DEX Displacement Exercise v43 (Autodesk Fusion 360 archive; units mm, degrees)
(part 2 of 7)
sketch "Sketch3" plane through (0, 0, 0) normal (1, 0, 0) x axis (0, 1, 0)
  line L1 (0, -98.35) -> (0, 35.65)
  line L2 (600, -98.35) -> (0, -98.35)
  line L3 (600, 35.65) -> (600, -98.35)
  line L4 (600, 35.65) -> (0, 35.65)
  line L5 (580, 20.65) -> (600, 20.65)
  line L6 (580, 35.65) -> (580, 20.65)
  line L7 (20, 20.65) -> (0, 20.65)
  line L8 (20, 35.65) -> (20, 20.65)
  line L9 (580, -83.35) -> (580, -98.35)
  line L10 (600, -83.35) -> (580, -83.35)
  line L11 (10, -83.35) -> (0, -83.35)
  line L12 (10, -48.35) -> (10, -83.35)
  line L13 (45, -48.35) -> (10, -48.35)
  line L14 (45, -83.35) -> (45, -48.35)
  line L15 (65, -83.35) -> (45, -83.35)
  line L16 (65, -98.35) -> (65, -83.35)
  line L17 (27.5, -48.35) -> (27.5, -68.65)
  line L18 (27.5, -68.65) -> (4.7, -98.65)
  line L19 (50.3, -98.65) -> (27.5, -68.65)
  line L20 (114.9, -83.45) -> (54.9, -83.45)
  line L21 (114.9, -23.45) -> (114.9, -83.45)
  line L22 (54.9, -23.45) -> (114.9, -23.45)
  line L23 (54.9, -83.45) -> (54.9, -23.45)
  line L24 (430, -48.35) -> (520, -48.35)
  line L25 (430, -78.35) -> (430, -48.35)
  line L26 (520, -78.35) -> (430, -78.35)
  line L27 (520, -48.35) -> (520, -78.35)
  line L28 (140, -48.35) -> (230, -48.35)
  line L29 (140, -78.35) -> (140, -48.35)
  line L30 (230, -78.35) -> (140, -78.35)
  line L31 (230, -48.35) -> (230, -78.35)
  line L32 (285, -78.35) -> (375, -78.35)
  line L33 (285, -48.35) -> (285, -78.35)
  line L34 (375, -48.35) -> (285, -48.35)
  line L35 (375, -78.35) -> (375, -48.35)
  circle C1 centre (4.7, -98.65) radius 9.7
  circle C2 centre (27.5, -68.65) radius 11.4592
  circle C3 centre (50.3, -98.65) radius 9.7
  circle C4 centre (27.5, -68.65) radius 40
  circle C5 centre (4.7, 35.95) radius 9.7
  circle C6 centre (595.3, 35.95) radius 9.7
  circle C7 centre (595.3, -98.65) radius 9.7
  circle C8 centre (595, 15.65) radius 1.575
  circle C9 centre (575, 15.65) radius 1.575
  circle C10 centre (575, 30.65) radius 1.575
  circle C11 centre (25, 30.65) radius 1.575
  circle C12 centre (25, 15.65) radius 1.575
  circle C13 centre (5, 15.65) radius 1.575
  circle C14 centre (595, -78.35) radius 1.575
  circle C15 centre (575, -78.35) radius 1.575
  circle C16 centre (575, -93.35) radius 1.575
  circle C17 centre (5, -78.35) radius 1.575
  circle C18 centre (70, -93.35) radius 1.575
  circle C19 centre (50, -43.35) radius 1.575
  circle C20 centre (5, -43.35) radius 1.575
  circle C21 centre (50, 25) radius 1.575
  circle C22 centre (65, 25) radius 1.575
  circle C23 centre (75, 25) radius 1.575
  circle C24 centre (90, 25) radius 1.575
  circle C25 centre (90, 17) radius 1.575
  circle C26 centre (75, 17) radius 1.575
  circle C27 centre (65, 17) radius 1.575
  circle C28 centre (50, 17) radius 1.575
  circle C29 centre (120, -93.35) radius 1.575
  circle C30 centre (120, -28.35) radius 1.575
  circle C31 centre (5, -28.35) radius 1.575
  circle C32 centre (50, -28.35) radius 1.575
  circle C33 centre (50, -78.35) radius 1.575
  circle C34 centre (5, -7.5) radius 1.575
  circle C35 centre (25, -7.5) radius 1.575
  circle C36 centre (510, 17) radius 1.575
  circle C37 centre (535, 17) radius 1.575
  circle C38 centre (510, 25) radius 1.575
  circle C39 centre (535, 25) radius 1.575
  circle C40 centre (525, 17) radius 1.575
  circle C41 centre (550, 25) radius 1.575
  circle C42 centre (550, 17) radius 1.575
  circle C43 centre (525, 25) radius 1.575
  point P2 (4.7, -98.65)
  point P4 (50.3, -98.65)
  point P9 (4.7, 35.95)
  point P10 (595.3, 35.95)
  point P11 (595.3, -98.65)
  point P13 (600, 20.65)
  point P15 (580, 35.65)
  point P16 (595, 15.65)
  point P17 (575, 15.65)
  point P18 (575, 30.65)
  point P20 (0, 20.65)
  point P22 (20, 35.65)
  point P24 (25, 15.65)
  point P25 (5, 15.65)
  point P23 (25, 30.65)
  point P26 (580, -98.35)
  point P28 (600, -83.35)
  point P29 (595, -78.35)
  point P30 (575, -78.35)
  point P31 (575, -93.35)
  point P32 (605, 35.95)
  point P33 (-5, -98.65)
  point P34 (0, -83.35)
  point P40 (65, -98.35)
  point P5 (27.5, -68.65)
  point P41 (27.5, -68.65)
  point P42 (27.5, -48.35)
  point P43 (4.7, -98.65)
  point P3 (27.5, -68.65)
  point P44 (27.5, -68.65)
  point P45 (27.5, -68.65)
  point P46 (50.3, -98.65)
  point P35 (10, -83.35)
  point P56 (75, 17)
  point P57 (65, 17)
  point P58 (50, 17)
  point P55 (90, 17)
  point P51 (50, 25)
  point P53 (75, 25)
  point P54 (90, 25)
  point P52 (65, 25)
  point P49 (50, -43.35)
  point P63 (50, -78.35)
  point P50 (5, -43.35)
  point P62 (50, -28.35)
  point P61 (5, -28.35)
  point P60 (120, -28.35)
  point P48 (70, -93.35)
  point P59 (120, -93.35)
  point P68 (5, -7.5)
  point P69 (25, -7.5)
  point P75 (525, 17)
  point P77 (535, 17)
  point P72 (510, 17)
  point P73 (550, 17)
  point P71 (510, 25)
  point P74 (535, 25)
  point P76 (550, 25)
  point P70 (525, 25)
  point P80 (430, -78.35)
  point P79 (430, -48.35)
  point P85 (230, -78.35)
  point P6 (0, 35.65)
  point P1 (0, 0)
  point P7 (0, -98.35)
  point P36 (10, -48.35)
  point P37 (45, -48.35)
  point P38 (45, -83.35)
  point P39 (65, -83.35)
  point P47 (5, -78.35)
  point P64 (54.9, -83.45)
  point P65 (114.9, -83.45)
  point P81 (520, -78.35)
  point P78 (520, -48.35)
  point P86 (375, -78.35)
  equal C1 C3
  horizontal P2 P4
  concentric C2 C4
  equal C1 C7
  equal C1 C6
  equal C1 C5
  horizontal P9 P10
  vertical P2 P9
  vertical P10 P11
  coincident L3 P13
  perpendicular L3 L5
  coincident L4 P15
  perpendicular L4 L6
  horizontal P16 P17
  vertical P17 P18
  equal C9 C10
  equal C8 C10
  coincident L1 P20
  perpendicular L1 L7
  coincident L4 P22
  perpendicular L4 L8
  horizontal P24 P25
  vertical P23 P24
  equal C12 C13
  equal C11 C12
  equal C9 C12
  coincident L2 P26
  perpendicular L2 L9
  coincident L3 P28
  perpendicular L3 L10
  equal C14 C15
  equal C15 C16
  equal C9 C15
  vertical P16 P29
  vertical P17 P30
  vertical P30 P31
  horizontal P29 P30
  coincident C6 P32
  horizontal P10 P32
  coincident C1 P33
  horizontal P2 P33
  coincident L1 P34
  perpendicular L1 L11
  perpendicular L11 L12
  perpendicular L12 L13
  perpendicular L13 L14
  perpendicular L12 L15
  coincident L2 P40
  perpendicular L2 L16
  coincident P5 P41
  vertical L17
  midpoint L13 P42
  coincident P2 P43
  coincident P3 P44
  coincident P3 P45
  coincident P4 P46
  equal L18 L19
  coincident P35 L15
  equal C18 C19
  equal C18 C20
  equal C17 C18
  equal C21 C23
  equal C23 C24
  equal C22 C24
  equal C22 C26
  equal C26 C28
  equal C25 C28
  equal C25 C27
  horizontal P56 P57
  horizontal P56 P58
  horizontal P55 P58
  horizontal P51 P53
  horizontal P53 P54
  horizontal P52 P54
  vertical P54 P55
  vertical P53 P56
  vertical P52 P57
  vertical P51 P58
  vertical P49 P63
  horizontal P49 P50
  equal C20 C32
  equal C20 C31
  equal C19 C33
  vertical P49 P62
  vertical P50 P61
  horizontal P61 P62
  horizontal P60 P62
  horizontal P48 P59
  equal C29 C30
  equal C30 C32
  horizontal L20
  vertical L21
  horizontal L22
  vertical L23
  vertical P59 P60
  equal L20 L21
  equal C34 C35
  horizontal P68 P69
  equal C38 C39
  equal C39 C41
  equal C41 C43
  equal C37 C43
  equal C36 C37
  equal C36 C42
  equal C40 C42
  horizontal P75 P77
  horizontal P72 P77
  horizontal P72 P73
  horizontal P71 P74
  horizontal P74 P76
  horizontal P70 P76
  vertical P73 P76
  vertical P74 P77
  vertical P70 P75
  vertical P71 P72
  horizontal P55 P72
  horizontal L24
  vertical L25
  horizontal L26
  vertical L27
  horizontal L28
  vertical L29
  horizontal L30
  vertical L31
  coincident P80 L30
  coincident P79 L28
  equal L26 L30
  horizontal L32
  vertical L33
  horizontal L34
  vertical L35
  coincident P79 L34
  coincident P85 L32
  equal L24 L34
  dimension "d1486" diameter C1 = 19.4
  dimension "d1487" diameter C2 = 22.9183 (= "( 3 * 24 / PI ) * 1 mm")
  dimension "d1490" distance P2 P3 = 30
  dimension "d1491" diameter C4 = 80
  dimension "d1494" distance P2 L2 = 0.3 (= "10 mm - d1486 / 2")
  dimension "d1495" distance P6 P9 = 0.3 (= "d1494")
  dimension "d1500" distance P1 L4 = 35.65
  dimension "d1501" distance P16 P17 = 20
  dimension "d1502" distance L3 P16 = 5
  dimension "d1503" distance P17 P18 = 15
  dimension "d1504" distance L6 P18 = 5
  dimension "d1505" distance L5 P16 = 5
  dimension "d1506" distance L4 P18 = 5
  dimension "d1507" diameter C10 = 3.15
  dimension "d1522" distance L8 P23 = 5
  dimension "d1523" distance L7 P25 = 5
  dimension "d1524" distance L1 P25 = 5
  dimension "d1525" distance P24 P25 = 20
  dimension "d1526" distance P23 P24 = 15
  dimension "d1527" distance L4 P23 = 5
  dimension "d1528" distance L2 P11 = 0.3 (= "d1496")
  dimension "d1529" distance L9 P31 = 5
  dimension "d1530" distance L10 P29 = 5
  dimension "d1531" distance P30 P31 = 15
  dimension "d1532" distance L2 P31 = 5
  dimension "d1557" distance L3 P32 = 5
  dimension "d1558" distance L1 P33 = 5
  dimension "d1559" distance P6 L7 = 15
  dimension "d1560" distance P7 L11 = 15
  dimension "d1561" distance L1 L12 = 10
  dimension "d1562" distance L2 L13 = 50
  dimension "d1563" = 18.2592
  dimension "d1564" distance P36 P37 = 35
  dimension "d1565" distance P38 P39 = 20
  dimension "d1566" diameter C18 = 3.15
  dimension "d1567" distance L16 P48 = 5
  dimension "d1568" distance L2 P48 = 5
  dimension "d1569" distance L14 P49 = 5
  dimension "d1570" distance L13 P50 = 5
  dimension "d1571" distance L12 P47 = 5
  dimension "d1572" distance L11 P47 = 5
  dimension "d1597" diameter C28 = 3.15
  dimension "d1599" distance P1 P51 = 25
  dimension "d1600" distance P57 P58 = 15
  dimension "d1601" distance P56 P57 = 10
  dimension "d1602" distance P55 P56 = 15
  dimension "d1603" distance P1 P58 = 50
  dimension "d1637" distance L12 P50 = 5
  dimension "d1638" distance L15 P63 = 5
  dimension "d1639" distance P50 P61 = 15
  dimension "d1640" distance P48 P59 = 50
  dimension "d1641" distance P63 L23 = 4.9
  dimension "d1642" distance P64 P65 = 60
  dimension "d1643" distance P48 L20 = 9.9
  dimension "d1645" distance P68 P69 = 20
  dimension "d1647" distance P1 P68 = 7.5
  dimension "d1648" distance P1 P68 = 5
  dimension "d1649" diameter C35 = 3.15
  dimension "d1687" distance P51 P58 = 8
  dimension "d1688" diameter C36 = 3.15
  dimension "d1689" distance P72 P75 = 15
  dimension "d1690" distance P75 P77 = 10
  dimension "d1691" distance P73 P77 = 15
  dimension "d1692" distance P71 P72 = 8
  dimension "d1693" distance P13 P76 = 50
  dimension "d1694" distance L2 L26 = 20
  dimension "d1695" distance P80 P81 = 90
  dimension "d1696" distance P78 P81 = 30
  dimension "d1697" distance L3 L27 = 80
  dimension "d1698" distance P1 L29 = 140
  dimension "d1701" distance L25 P86 = 55
  dimension "d1702" = 60
extrude "Extrude6" cut sketch "Sketch3" profile of L1 L2 C5 C6 C7 L3 L4 L5 L6 C8 C9 C10 L7 L8 C11 C12 C13 L9 L10 C14 C15 C16 L11 L12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 distance 25
fillet "Fillet3" radius 2
fillet "Fillet4" radius 1
fillet "Fillet6" radius 5
component_insert "Component Insert17"
joint "Assemble21" OffsetX 0 OffsetY 0 OffsetZ 0 AngleZ 0 alignAngle 360 alignOffsetX 0 alignOffsetY 0 alignOffsetZ 0
component_insert "Component Insert18"
joint "Assemble22" OffsetX 0 OffsetY 0 OffsetZ 0 AngleZ 0 alignAngle 0 alignOffsetX 0 alignOffsetY 0 alignOffsetZ 0
component_insert "Component Insert19"
joint "Assemble23" OffsetX 0 OffsetY 0 OffsetZ 0 AngleZ 0 alignAngle 180 alignOffsetX 0 alignOffsetY 0 alignOffsetZ 0
component_insert "Component Insert3"
joint "Assemble7" OffsetX 0 OffsetY 0 OffsetZ 0 AngleZ 0 alignAngle 0 alignOffsetX 0 alignOffsetY 0 alignOffsetZ 0
component_insert "Component Insert14"
joint "Assemble18" OffsetX 0 OffsetY 0 OffsetZ 0 AngleZ 0 alignAngle 180 alignOffsetX 0 alignOffsetY 0 alignOffsetZ 0
component_insert "Component Insert4"
joint "Assemble14" OffsetX 0 OffsetY 0 OffsetZ 0 AngleZ 0 alignAngle 180 alignOffsetX 0 alignOffsetY 0 alignOffsetZ 0
component_insert "Component Insert10"
joint "Assemble15" OffsetX 0 OffsetY 0 OffsetZ 0 AngleZ 0 alignAngle 0 alignOffsetX 0 alignOffsetY 0 alignOffsetZ 0
component_insert "Component Insert11"
joint "Assemble16" OffsetX 0 OffsetY 0 OffsetZ 0 AngleZ 0 alignAngle 0 alignOffsetX 0 alignOffsetY 0 alignOffsetZ 0
component_insert "Component Insert12"
joint "Assemble17" OffsetX 0 OffsetY 0 OffsetZ 0 AngleZ 0 alignAngle 180 alignOffsetX 0 alignOffsetY 0 alignOffsetZ 0
component_insert "Component Insert15"
joint "Assemble19" OffsetX 0 OffsetY 0 OffsetZ 0 AngleZ 0 alignAngle 180 alignOffsetX 0 alignOffsetY 0 alignOffsetZ 0
component_insert "Component Insert16"
joint "Assemble20" OffsetX 0 OffsetY 0 OffsetZ 0 AngleZ 0 alignAngle 0 alignOffsetX 0 alignOffsetY 0 alignOffsetZ 0
component_insert "Component Insert8"
joint "Assemble12" OffsetX 0 OffsetY 0 OffsetZ 0 AngleZ 0 alignAngle 0 alignOffsetX 0 alignOffsetY 0 alignOffsetZ 0
component_insert "Component Insert9"
joint "Assemble13" OffsetX 0 OffsetY 0 OffsetZ 0 AngleZ 0 alignAngle 0 alignOffsetX 0 alignOffsetY 0 alignOffsetZ 0 OffsetX 0 OffsetY 0 OffsetZ 0 AngleZ 0 OffsetX 0 OffsetY 0 OffsetZ 0 AngleZ 0
component_insert "Component Insert22"
joint "Assemble25" OffsetX 0 OffsetY 0 OffsetZ 0 AngleZ 0 alignAngle 180 alignOffsetX 0 alignOffsetY 0 alignOffsetZ 0
sketch "Sketch8" plane through (-36.8, 0, 0) normal (-1, 0, 0) x axis (0, -1, 0)
  line L1 (-167.5, 36.65) -> (-152.5, 36.65)
  line L2 (-167.5, 43.35) -> (-167.5, 36.65)
  line L3 (-152.5, 43.35) -> (-167.5, 43.35)
  line L4 (-152.5, 36.65) -> (-152.5, 43.35)
  line L5 (-97.5, 36.65) -> (-82.5, 36.65)
  line L6 (-97.5, 43.35) -> (-97.5, 36.65)
  line L7 (-82.5, 43.35) -> (-97.5, 43.35)
  line L8 (-82.5, 36.65) -> (-82.5, 43.35)
  line L9 (-27.5, 36.65) -> (-12.5, 36.65)
  line L10 (-27.5, 43.35) -> (-27.5, 36.65)
  line L11 (-12.5, 43.35) -> (-27.5, 43.35)
  line L12 (-12.5, 36.65) -> (-12.5, 43.35)
  line L13 (-32, 20) -> (-32, 12.5)
  line L14 (-8.5, 20.5) -> (-31.5, 20.5)
  line L15 (-8, -19.9) -> (-8, 20)
  line L16 (-1, -19.9) -> (-8, -19.9)
  line L17 (0, 92.35) -> (0, -18.9)
  line L18 (-179, 93.35) -> (-1, 93.35)
  line L19 (-180, -18.9) -> (-180, 92.35)
  line L20 (-172, -19.9) -> (-179, -19.9)
  line L21 (-172, 20) -> (-172, -19.9)
  line L22 (-148.5, 20.5) -> (-171.5, 20.5)
  line L23 (-148, 12.5) -> (-148, 20)
  line L24 (-142.5, 12) -> (-147.5, 12)
  line L25 (-142, -11.5) -> (-142, 11.5)
  line L26 (-147.5, -12) -> (-142.5, -12)
  line L27 (-148, -19.9) -> (-148, -12.5)
  line L28 (-32, -19.9) -> (-148, -19.9)
  line L29 (-32, -12.5) -> (-32, -19.9)
  line L30 (-37.5, -12) -> (-32.5, -12)
  line L31 (-38, 11.5) -> (-38, -11.5)
  line L32 (-32.5, 12) -> (-37.5, 12)
  circle C1 centre (-175, -15) radius 1.575
  circle C2 centre (-145, 15) radius 1.575
  circle C3 centre (-175, 15) radius 1.575
  circle C4 centre (-175, -5) radius 1.575
  circle C5 centre (-145, -15) radius 1.575
  circle C6 centre (-175, 5) radius 1.575
  circle C7 centre (-97.5, 47.5) radius 1.575
  circle C8 centre (-97.5, 32.5) radius 1.575
  circle C9 centre (-152.5, 47.5) radius 1.575
  circle C10 centre (-167.5, 32.5) radius 1.575
  circle C11 centre (-152.5, 32.5) radius 1.575
  circle C12 centre (-167.5, 47.5) radius 1.575
  circle C13 centre (-12.5, 47.5) radius 1.575
  circle C14 centre (-27.5, 32.5) radius 1.575
  circle C15 centre (-12.5, 32.5) radius 1.575
  circle C16 centre (-27.5, 47.5) radius 1.575
  circle C17 centre (-82.5, 32.5) radius 1.575
  circle C18 centre (-82.5, 47.5) radius 1.575
  arc A1 centre (-32.5, 12.5) radius 0.5 clockwise from (-32, 12.5) to (-32.5, 12)
  arc A2 centre (-31.5, 20) radius 0.5 clockwise from (-32, 20) to (-31.5, 20.5)
  arc A3 centre (-8.5, 20) radius 0.5 clockwise from (-8.5, 20.5) to (-8, 20)
  arc A4 centre (-171.5, 20) radius 0.5 clockwise from (-172, 20) to (-171.5, 20.5)
  arc A5 centre (-148.5, 20) radius 0.5 clockwise from (-148.5, 20.5) to (-148, 20)
  arc A6 centre (-147.5, 12.5) radius 0.5 clockwise from (-147.5, 12) to (-148, 12.5)
  arc A7 centre (-142.5, 11.5) radius 0.5 clockwise from (-142.5, 12) to (-142, 11.5)
  arc A8 centre (-142.5, -11.5) radius 0.5 clockwise from (-142, -11.5) to (-142.5, -12)
  arc A9 centre (-147.5, -12.5) radius 0.5 clockwise from (-148, -12.5) to (-147.5, -12)
  arc A10 centre (-32.5, -12.5) radius 0.5 clockwise from (-32.5, -12) to (-32, -12.5)
  arc A11 centre (-37.5, -11.5) radius 0.5 clockwise from (-37.5, -12) to (-38, -11.5)
  arc A12 centre (-37.5, 11.5) radius 0.5 clockwise from (-38, 11.5) to (-37.5, 12)
  circle C19 centre (-5, 5) radius 1.575
  circle C20 centre (-35, -15) radius 1.575
  circle C21 centre (-5, -5) radius 1.575
  circle C22 centre (-5, 15) radius 1.575
  circle C23 centre (-35, 15) radius 1.575
  circle C24 centre (-5, -15) radius 1.575
  circle C25 centre (-5, 88.35) radius 1.575
  arc A13 centre (-1, -18.9) radius 1 clockwise from (0, -18.9) to (-1, -19.9)
  arc A14 centre (-1, 92.35) radius 1 clockwise from (-1, 93.35) to (0, 92.35)
  arc A15 centre (-179, 92.35) radius 1 clockwise from (-180, 92.35) to (-179, 93.35)
  arc A16 centre (-179, -18.9) radius 1 clockwise from (-179, -19.9) to (-180, -18.9)
  point P84 (-5, 88.35)
  dimension "d1310" diameter C25 = 3.15
  dimension "d1311" distance L18 P84 = 5
  dimension "d1312" distance L17 P84 = 5
extrude "Extrude14" cut sketch "Sketch8" profile of C25 no distance stored
rectangular_pattern "R-Pattern1" countU 18 uSpaceDistance 10 vSpaceDistance 10
component_insert "Component Insert23"
joint "Assemble26" OffsetX 0 OffsetY 0 OffsetZ 0 AngleZ 0 alignAngle 0 alignOffsetX 0 alignOffsetY 0 alignOffsetZ 0 OffsetX 0 OffsetY 0 OffsetZ 0 AngleZ 0
component_insert "Component Insert20"
joint "Assemble27" OffsetX 0 OffsetY 0 OffsetZ 0 AngleZ 0 alignAngle 0 alignOffsetX 0 alignOffsetY 0 alignOffsetZ 0 OffsetX 0 OffsetY 0 OffsetZ 0 AngleZ 0
component_insert "Component Insert24"
joint "Assemble28" OffsetX 0 OffsetY 0 OffsetZ 0 AngleZ 0 OffsetX 0 OffsetY 0 OffsetZ 0 AngleZ 0 alignAngle 0 alignOffsetX 0 alignOffsetY 0 alignOffsetZ 0 OffsetX 0 OffsetY 0 OffsetZ 0 AngleZ 0 OffsetX 0 OffsetY 0 OffsetZ 0 AngleZ 0 OffsetX 0 OffsetY 0 OffsetZ 0 AngleZ 0 OffsetX 0 OffsetY 0 OffsetZ 0 AngleZ 0
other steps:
create_component "CreateComponent4"
create_component "CreateComponent5"
joint_origin "JointOrigin1" OffsetX 0 OffsetY 0 OffsetZ 0 AngleZ 0
joint_origin "JointOrigin7" OffsetX 0 OffsetY 0 OffsetZ 0 AngleZ 0
joint_origin "JointOrigin5" OffsetX 0 OffsetY 0 OffsetZ 0 AngleZ 0
joint_origin "JointOrigin10" OffsetX 0 OffsetY 0 OffsetZ 0 AngleZ 0
joint_origin "JointOrigin11" OffsetX 0 OffsetY 0 OffsetZ 0 AngleZ 0
joint_origin "JointOrigin12" OffsetX 0 OffsetY 0 OffsetZ 0 AngleZ 0
joint_origin "JointOrigin13" OffsetX 0 OffsetY 0 OffsetZ 0 AngleZ 0
joint_origin "JointOrigin14" OffsetX 0 OffsetY 0 OffsetZ 0 AngleZ 0
joint_origin "JointOrigin15" OffsetX 0 OffsetY 0 OffsetZ 0 AngleZ 0
joint_origin "JointOrigin16" OffsetX 0 OffsetY 0 OffsetZ 0 AngleZ 0
joint_origin "JointOrigin17" OffsetX 0 OffsetY 0 OffsetZ 0 AngleZ 0
joint_origin "JointOrigin2" OffsetX 0 OffsetY 0 OffsetZ 0 AngleZ 0
joint_origin "JointOrigin3" OffsetX 0 OffsetY 0 OffsetZ 0 AngleZ 0
joint_origin "JointOrigin4" OffsetX 0 OffsetY 0 OffsetZ 0 AngleZ 0
joint_origin "JointOrigin7" OffsetX 0 OffsetY 0 OffsetZ 0 AngleZ 0
joint_origin "JointOrigin9" OffsetX 0 OffsetY 0 OffsetZ 0 AngleZ 0
joint_origin "JointOrigin11" OffsetX 0 OffsetY 0 OffsetZ 0 AngleZ 0
joint_origin "JointOrigin12" OffsetX 0 OffsetY 0 OffsetZ 0 AngleZ 0
named bodies: "dex-rail_left-wing", "dex-rail_spine", "dex-rail_right-wing"

design "rct-lb-perp-pincer-x"
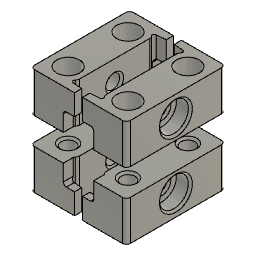
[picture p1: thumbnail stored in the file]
parameter "m3insert_d" = 5.5
parameter "m3thru_d" = 3.5
parameter "t_sheet_MAIN" = 6.7
sketch "Sketch1" plane through (0, 0, 0) normal (0, 0, 1) x axis (1, 0, 0)
  line L1 (0, -12.4) -> (0, 12.4)
  line L2 (3.35, 12.4) -> (-3.35, 12.4)
  line L3 (3.35, -12.4) -> (3.35, 12.4)
  line L4 (-3.35, -12.4) -> (3.35, -12.4)
  line L5 (-3.35, 12.4) -> (-3.35, -12.4)
  line L6 (-1, 10.6056) -> (-1, 12.4)
  line L7 (-3.35, 10.4) -> (-1, 10.6056)
  line L8 (-3.35, 0) -> (-3.35, 9.4038)
  line L9 (-12, 12.4) -> (-1, 12.4)
  line L10 (-12, 0) -> (-12, 12.4)
  line L11 (-3.35, 0) -> (-12, 0)
  line L12 (-3.8064, 12.4) -> (-3.8064, 9.9019)
  circle C1 centre (-7.5, 7.5) radius 2.75
  circle C2 centre (-7.5, 7.5) radius 1.75
  arc A1 centre (-3.3064, 9.9019) radius 0.5 clockwise from (-3.35, 9.4038) to (-3.35, 10.4)
  point P1 (0, 0)
  point P2 (0, 12.4)
  point P3 (0, -12.4)
  point P10 (-1, 12.4)
  point P12 (-3.35, 10.4)
  point P13 (-3.35, 9.4038)
  point P14 (-3.35, 0)
  point P18 (-3.35, 0)
  point P19 (-3.8064, 9.9019)
  point P20 (-3.8064, 12.4)
  point P21 (-10.25, 7.5)
  point P8 (-7.5, 7.5)
  point P6 (3.35, -12.4)
  point P7 (-3.35, -12.4)
  point P4 (-3.35, 12.4)
  point P16 (-12, 12.4)
  vertical L1
  midpoint P1 L1
  horizontal L2
  vertical L3
  horizontal L4
  vertical L5
  midpoint P2 L2
  midpoint P3 L4
  concentric C1 C2
  coincident L2 P10
  perpendicular L2 L6
  coincident L5 P12
  coincident L5 P13
  midpoint L5 P14
  parallel L5 L8
  tangent L7 A1
  perpendicular L6 L9
  perpendicular L9 L10
  perpendicular L10 L11
  coincident P14 P18
  midpoint A1 P19
  coincident L9 P20
  tangent A1 L12
  perpendicular L9 L12
  coincident C1 P21
  horizontal P8 P21
  dimension "d91" distance P2 P3 = 24.8
  dimension "d92" distance P6 P7 = 6.7 (= "t_sheet_MAIN")
  dimension "d95" distance P1 P8 = 7.5
  dimension "d98" diameter C2 = 3.5 (= "m3thru_d")
  dimension "d99" radius A1 = 0.5
  dimension "d101" angle L6 L7 = 85
  dimension "d102" distance P4 P12 = 2
  dimension "d103" distance P2 L6 = 1
  dimension "d104" diameter C1 = 5.5 (= "m3insert_d")
  dimension "d127" distance P1 P8 = 7.5
  dimension "d128" distance L1 P16 = 12
  dimension "d147" distance L10 P21 = 1.75
extrude "Extrude14" new body sketch "Sketch1" profile of C1 C2 L6 L7 L8 A1 L9 L10 L11 L12 against normal blind 10 bodies "rct-lb-perp-pincer-left"
extrude "Extrude15" cut sketch "Sketch1" profile of L6 L7 A1 L9 L12 against normal blind 4.8
fillet "Fillet5" radius 0.75
sketch "Sketch7" plane through (-3.35, 0, 0) normal (1, 0, 0) x axis (0, 1, 0)
  line L1 (0, 0) -> (9.4038, 0)
  line L2 (0, -10) -> (0, 0)
  line L3 (9.4038, -10) -> (0, -10)
  line L4 (9.4038, 0) -> (9.4038, -10)
  circle C1 centre (0, -4.8) radius 2.75
  circle C2 centre (0, -4.8) radius 1.75
  circle C3 centre (0, -4.8) radius 3.625
  point P6 (0, -4.8)
  point P1 (0, 0)
  point P7 (0, -4.8)
  coincident L2 P6
  concentric C1 C2
  concentric C1 C3
  dimension "d111" diameter C1 = 5.5 (= "m3insert_d")
  dimension "d112" diameter C2 = 3.5 (= "m3thru_d")
  dimension "d113" distance P1 P7 = 4.8
  dimension "d132" diameter C3 = 7.25
extrude "Extrude16" cut sketch "Sketch7" profile of L2 C2 no distance stored
extrude "Extrude17" cut sketch "Sketch1" profile of C2 no distance stored
work_plane "WorkPlane1" AlongDistance 3.35 (= "t_sheet_MAIN / 2")
fillet "Fillet6" radius 1
mirror "Mirror4" bodies "rct-lb-perp-pincer-left (1)"
extrude "Extrude18" sketch "Sketch1" profile of C1 C2 blind 4
chamfer "Chamfer4" distance 0.7
chamfer "Chamfer5" distance 0.5
chamfer "Chamfer10" distance 1.4
sketch "Sketch9" plane through (0, 0, 16.7) normal (0, 0, 1) x axis (-1, 0, 0)
  line L1 (1, -10.6056) -> (3.35, -10.4)
  line L2 (1, -12.4) -> (1, -10.6056)
  line L3 (12, -12.4) -> (1, -12.4)
  line L4 (12, 0) -> (12, -12.4)
  line L5 (3.35, 0) -> (12, 0)
  line L6 (3.35, -8.8244) -> (3.35, 0)
  arc A1 centre (4.35, -8.8244) radius 1 clockwise from (3.6543, -9.5427) to (3.35, -8.8244)
  arc A2 centre (3.3064, -9.9019) radius 0.5 clockwise from (3.6543, -9.5427) to (3.35, -10.4)
  circle C1 centre (7.5, -7.5) radius 1.75
  circle C2 centre (7.5, -7.5) radius 2.85
  concentric C1 C2
  dimension "d148" diameter C2 = 5.7
extrude "Extrude21" cut sketch "Sketch9" profile of C1 C2 against normal blind 5
chamfer "Chamfer11" distance 1
mirror "Mirror2"
combine "Combine2"
mirror "Mirror5" bodies "rct-lb-perp-pincer-left (1) (1)"
combine "Combine3" bodies "rct-lb-perp-pincer-left (1) (1)"
mirror "Mirror3" bodies "rct-lb-perp-pincer-right"
mirror "Mirror7" bodies "rct-lb-perp-pincer-left (1) (1)"
sketch "Sketch8" plane through (-3.35, 0, 0) normal (1, 0, 0) x axis (0, 1, 0)
  line L1 (-8.8244, 16.7) -> (8.8244, 16.7)
  line L2 (-8.8244, 6.7) -> (-8.8244, 16.7)
  line L3 (8.8244, 6.7) -> (-8.8244, 6.7)
  line L4 (8.8244, 16.7) -> (8.8244, 6.7)
  circle C1 centre (0, 11.5) radius 1.75
  circle C2 centre (0, 11.5) radius 2.75
  circle C3 centre (0, 11.5) radius 3.625
  concentric C1 C2
  concentric C2 C3
  dimension "d144" diameter C2 = 5.5 (= "m3insert_d")
  dimension "d145" diameter C3 = 7.25
extrude "Extrude19" sketch "Sketch7" + "Sketch8" profile of S1:L2 S1:C1 S1:C2 S2:C1 S2:C2 blind 3.8
chamfer "Chamfer6" distance 0.7
chamfer "Chamfer7" distance 0.5
extrude "Extrude20" sketch "Sketch7" + "Sketch8" profile of S1:L2 S1:C1 S1:C2 S1:C3 S2:C1 S2:C2 S2:C3 blind -3.5
chamfer "Chamfer9" distance 0.5
fillet "Fillet8" radius 1
named bodies: "rct-lb-perp-pincer-left", "rct-lb-perp-pincer-right", "rct-lb-perp-pincer-left (1)", "rct-lb-perp-pincer-left (1) (1)"

design "RCT N17 Blister Mirror"
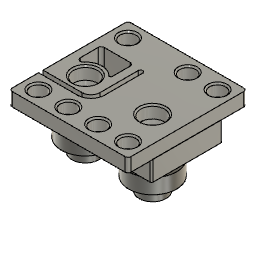
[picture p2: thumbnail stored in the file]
parameter "t_sheet_MAIN" = 6.7 comment "thickness of *most* of the gantry material"
parameter "t_sheet_SECOND" = 6.35 (= "1 / 4 * 1") comment "thickness of the webs"
parameter "od_bearings" = 16
parameter "id_bearings" = 5
parameter "t_bearings" = 5
parameter "p_belt" = 2
parameter "w_belt" = 10
parameter "t_belt" = 1.4
parameter "l_top_belt_to_rail" = 3
parameter "r_cutoutTool" = 2.05 (= "4.1 mm / 2")
parameter "hw_m3_thru" = 3.5
parameter "hw_m3_head" = 5.5
parameter "hw_m3_washer" = 7
parameter "hw_m3_thread" = 2.5
parameter "tab_breather" = 0.2 comment "tab clearance"
parameter "hw_m5_thread" = 4.2
parameter "hw_m5_head" = 8.5
parameter "hw_m5_washer" = 10
parameter "hw_m5_thru" = 5.25
parameter "hw_m6_thru" = 6.5
parameter "hw_m6_head" = 10
parameter "hw_m6_washer" = 12
parameter "l_beltblock" = 15
parameter "hw_plstf6_thread" = 2.94
parameter "hw_plstf6_thru" = 4
parameter "hw_plstf6_head" = 6.86
parameter "hw_plstf6_washer" = 7.92
parameter "hw_m3_flathead" = 6
parameter "hw_m4insert_d" = 6
parameter "hw_m4insert_l" = 4.8
parameter "hw_m4_tappedwj" = 3.3
parameter "hw_m4_thru" = 4.25
parameter "hw_m4_head" = 7
parameter "hw_m4_headheight" = 4
parameter "preload_bearings" = 0.55
parameter "hw_m3insert_d" = 5.4
parameter "hw_m3insert_l" = 3.8
parameter "dist_clearance" = 0.5
parameter "hw_shoulder_headDiameter" = 9
parameter "hw_shoulder_headHeight" = 4
parameter "l_travel" = 405 comment "will be rounded to 10s"
parameter "User Parameter" = 0 (= "min 10")
parameter "nh_rail_width" = "nh_gantry_width - 3"
parameter "l_shoulder_thread" = 10
parameter "hw_n6_thru" = 4.064
parameter "hw_n6_thread" = 3.1
parameter "hw_n6_flathead" = 6.6548
parameter "hw_n6_head" = 6.858
parameter "carriage_offsets" = 0.25
parameter "hw_momentPin_reald" = 3.683
parameter "pinch_by" = 0.2
parameter "d285" = 2
parameter "d344" = 3.5
parameter "d482" = 3.35 (= "t_sheet_MAIN / 2")
parameter "d578" = 0.5
parameter "d683" = 3.683 (= "hw_momentPin_reald")
parameter "d689" = 0.5
parameter "d698" = 5
parameter "d705" = 3.5415 (= "d683 / 2 + 1.7 mm")
parameter "d837" = 0.25
sketch "Plate Cuts" plane through (0, 0, 0) normal (0, 0, 1) x axis (1, 0, 0)
  line L1 (0, 60) -> (0, 0)
  line L2 (3.35, 0) -> (3.35, 60)
  line L3 (-3.35, 60) -> (-3.35, 0)
  line L4 (-15, 10) -> (-5, 10)
  line L5 (-15, 40) -> (-5, 40)
  line L6 (15, 10) -> (5, 10)
  line L7 (-20, 37) -> (-20, 13)
  line L8 (-2, 37) -> (-20, 37)
  line L9 (-2, 43) -> (-2, 37)
  line L10 (12, 43) -> (-2, 43)
  line L11 (12, 37) -> (12, 43)
  line L12 (20.5, 37) -> (12, 37)
  line L13 (20.5, 13) -> (20.5, 37)
  line L14 (-20, 13) -> (20.5, 13)
  circle C1 centre (-5, 10) radius 1.575
  circle C2 centre (-15, 10) radius 1.575
  circle C3 centre (-11.25, 22) radius 8
  circle C4 centre (-15, 40) radius 1.575
  circle C5 centre (-5, 40) radius 1.575
  circle C6 centre (11.25, 22) radius 8
  circle C7 centre (15, 40) radius 1.575
  circle C8 centre (5, 10) radius 1.575
  circle C9 centre (15, 10) radius 1.575
  circle C10 centre (-11.25, 22) radius 8.25
  circle C11 centre (11.25, 22) radius 8.25
  point P1 (0, 0)
  point P2 (0, 0)
  point P3 (0, 60)
  point P7 (-3.35, 60)
  point P4 (3.35, 60)
  point P6 (-3.35, 0)
  point P5 (3.35, 0)
  point P8 (-5, 10)
  point P10 (-5, 10)
  point P9 (-15, 10)
  point P11 (-15, 10)
  point P14 (-15, 40)
  point P15 (-15, 40)
  point P13 (-5, 40)
  point P16 (-5, 40)
  point P12 (-11.25, 22)
  point P17 (11.25, 22)
  point P18 (15, 40)
  point P19 (5, 10)
  point P21 (5, 10)
  point P20 (15, 10)
  point P22 (15, 10)
  point P27 (-2, 37)
  point P25 (-20, 13)
  point P33 (-20, 13)
  coincident P1 P2
  vertical L1
  parallel L1 L2
  parallel L1 L3
  horizontal P3 P7
  horizontal P3 P4
  horizontal P1 P6
  horizontal P1 P5
  coincident P8 P10
  horizontal L4
  coincident P9 P11
  equal C1 C2
  horizontal L5
  coincident P14 P15
  coincident P13 P16
  equal L4 L5
  equal C2 C4
  equal C1 C5
  equal C3 C6
  horizontal P12 P17
  equal C5 C7
  horizontal P16 P18
  horizontal L6
  coincident P19 P21
  coincident P20 P22
  equal C2 C8
  equal C2 C9
  equal L4 L6
  concentric C3 C10
  concentric C6 C11
  vertical L7
  perpendicular L3 L8
  perpendicular L8 L9
  perpendicular L9 L10
  perpendicular L8 L11
  perpendicular L11 L12
  perpendicular L12 L13
  coincident P27 L12
  perpendicular L13 L14
  coincident P25 P33
  dimension "d1151" distance P2 P3 = 60
  dimension "d1152" distance L1 L3 = 3.35 (= "t_sheet_MAIN / 2")
  dimension "d1153" distance L1 L2 = 3.35 (= "d1152")
  dimension "d1154" distance L1 P8 = 5
  dimension "d1156" distance P10 P11 = 10
  dimension "d1157" diameter C2 = 3.15
  dimension "d1158" distance P1 L4 = 10
  dimension "d1159" diameter C3 = 16 (= "od_bearings")
  dimension "d1160" distance P9 L5 = 30
  dimension "d1161" distance L1 P16 = 5
  dimension "d1162" distance L1 P12 = 11.25 (= "od_bearings / 2 + t_sheet_MAIN / 2 - pinch_by / 2")
  dimension "d1163" distance P9 P12 = 12
  dimension "d1164" distance L1 P17 = 11.25 (= "d1162")
  dimension "d1165" distance P16 P18 = 20
  dimension "d1166" distance P1 L6 = 10
  dimension "d1167" distance L1 P21 = 5
  dimension "d1168" distance C6 C11 = 0.25
  dimension "d1169" distance C3 C10 = 0.25 (= "d1168")
  dimension "d1171" distance P16 L9 = 3
  dimension "d1172" distance P16 L8 = 3
  dimension "d1174" distance P16 L10 = 3
  dimension "d1175" distance P18 L11 = 3
  dimension "d1176" distance P18 L13 = 5.5
  dimension "d1177" distance P21 L14 = 3
  dimension "d1229" distance P15 L7 = 5
  dimension "d1000" ProfileOffset = 2
  dimension "d1001" AlongDistance = 10
  dimension "d1002" TaperAngle = 0
  dimension "d1004" TaperAngle = 0
  dimension "d1005" ProfileOffset = -0.5
  dimension "d1006" AlongDistance = -55
  dimension "d1007" TaperAngle = 0
  dimension "d467" angle = 5
  dimension "d469" angle = 5
  dimension "d470" angle = 5
  dimension "d471" diameter = 3.5 (= "hw_m3_thru")
  dimension "d472" diameter = 7 (= "hw_m3_washer")
  dimension "d475" distance = 2.4 (= "t_belt + 1 mm")
  dimension "d476" distance = 2.4 (= "d475")
  dimension "d477" distance = 4.477
  dimension "d479" distance = 1
  dimension "d480" distance = 0.75
  dimension "d485" distance = 0.75 (= "d480")
  dimension "d487" diameter = 3.1 (= "hw_n6_thread")
  dimension "d488" diameter = 4.064 (= "hw_n6_thru")
  dimension "d489" Side1Offset = 0.5
  dimension "d490" TaperAngle = 0
  dimension "d491" Side1Offset = 0
  dimension "d492" TaperAngle = 0
  dimension "d493" Side1Offset = 0
  dimension "d494" TaperAngle = 0
  dimension "d495" Side1Offset = 1
  dimension "d496" TaperAngle = 0
  dimension "d497" distance = 9
  dimension "d498" angle = 5 (= "d469")
  dimension "d500" distance = 5
  dimension "d501" radius = 11.075 (= "( 22.15 / 2 ) * 1 mm")
  dimension "d502" Side1Offset = 0
  dimension "d503" TaperAngle = 0
  dimension "d504" diameter = 5.3 (= "hw_m3insert_d - 0.1 mm")
  dimension "d506" diameter = 3.5 (= "hw_m3_thru")
  dimension "d507" Side1Offset = 0
  dimension "d508" TaperAngle = 0
  dimension "d509" AlongDistance = -5
  dimension "d510" TaperAngle = 0
  dimension "d529" AlongDistance = 100
  dimension "d530" TaperAngle = 0
  dimension "d531" countU = 13 (= "nh_gantry_length + 1")
  dimension "d532" CountV = 9 (= "nh_gantry_width + 1")
  dimension "d533" uSpaceDistance = 10
  dimension "d534" vSpaceDistance = -10
  dimension "d535" diameter = 3.3 (= "hw_m4_tappedwj")
  dimension "d541" uSpaceDistance = 10
  dimension "d542" vSpaceDistance = 10
  dimension "d560" distance = 6.6 (= "t_sheet_MAIN")
  dimension "d563" distance = 5 (= "t_bearings")
  dimension "d564" distance = 16 (= "od_bearings")
  dimension "d565" angle = 45 (= "d566")
  dimension "d566" angle = 45
  dimension "d567" distance = 10 (= "l_shoulder_thread")
  dimension "d568" distance = 6.6 (= "t_sheet_MAIN")
  dimension "d569" distance = 45 (= "( ( nh_gantry_width * 10 ) * 1 mm + 10 mm ) / 2")
  dimension "d571" distance = 4.5 (= "hw_shoulder_headHeight + 0.5 mm")
  dimension "d572" distance = 4.5 (= "hw_shoulder_headDiameter / 2")
  dimension "d574" distance = 8.8037
  dimension "d576" distance = 0.5
  dimension "d577" distance = 0.5
  dimension "d580" distance = 0.5
  dimension "d581" distance = 3.5 (= "hw_m4insert_d / 2 + 0.5 mm")
  dimension "d582" distance = 3.5 (= "d581")
  dimension "d583" distance = 2.1
  dimension "d584" distance = 0.8383
  dimension "d586" distance = 1.269 (= "0.5 mm + 0.769 mm")
  dimension "d587" distance = 5
  dimension "d588" distance = 10
  dimension "d589" distance = 5
  dimension "d590" AlongDistance = 65 (= "( nh_gantry_length * 10 + 10 ) / 2 * 1 mm")
  dimension "d591" TaperAngle = 0
  dimension "d597" ProfileOffset = 0.25 (= "carriage_offsets")
  dimension "d599" TaperAngle = 0
  dimension "d601" diameter = 16 (= "od_bearings")
  dimension "d602" diameter = 6 (= "hw_m4insert_d")
  dimension "d603" diameter = 4
  dimension "d604" distance = 0.25
  dimension "d606" AlongDistance = -20
  dimension "d607" TaperAngle = 0
  dimension "d608" ProfileOffset = 0.5
  dimension "d609" AlongDistance = 5 (= "t_bearings")
  dimension "d610" TaperAngle = 0
  dimension "d612" distance = 0.25
  dimension "d613" diameter = 4
  dimension "d614" diameter = 6 (= "hw_m4insert_d")
  dimension "d615" diameter = 16 (= "od_bearings")
  dimension "d616" AlongDistance = -20
  dimension "d617" TaperAngle = 0
  dimension "d618" ProfileOffset = 0.5
  dimension "d619" AlongDistance = 5 (= "t_bearings")
  dimension "d620" TaperAngle = 0
  dimension "d621" AlongDistance = 670 (= "l_actual_complete")
  dimension "d622" TaperAngle = 0
  dimension "d623" distance = 0.1
  dimension "d624" distance = 1.6455
  dimension "d625" distance = 3.4128
  dimension "d626" distance = 13.2 (= "0.5 in + 0.5 mm")
  dimension "d628" distance = 5
  dimension "d630" distance = 30
  dimension "d631" diameter = 4.064 (= "hw_n6_thru")
  dimension "d636" diameter = 6.6548 (= "hw_n6_flathead")
  dimension "d637" diameter = 3.1 (= "hw_n6_thread")
  dimension "d638" distance = 4
  dimension "d639" distance = 4 (= "d638")
  dimension "d641" TaperAngle = 0
  dimension "d642" ProfileOffset = 0
  dimension "d643" Side1Offset = 0
  dimension "d644" TaperAngle = 0
  dimension "d645" ProfileOffset = 0
  dimension "d646" Side1Offset = 0
  dimension "d647" TaperAngle = 0
  dimension "d648" distance = 5
  dimension "d649" distance = 0.75
  dimension "d650" ProfileOffset = 0
  dimension "d651" Side1Offset = 0
  dimension "d652" TaperAngle = 0
  dimension "d653" AlongDistance = 21
  dimension "d654" TaperAngle = 0
  dimension "d655" distance = 1
  dimension "d656" ProfileOffset = 0
  dimension "d657" Side1Offset = 0
  dimension "d658" TaperAngle = 0
  dimension "d659" AlongDistance = 12
  dimension "d660" TaperAngle = 0
  dimension "d661" Side1Offset = 0
  dimension "d662" TaperAngle = 0
  dimension "d667" Radius = 4
  dimension "d669" Radius = 4
  dimension "d670" Radius = 1
  dimension "d673" Radius = 0.5
  dimension "d674" Radius = 0.5
  dimension "d675" Radius = 0.5
  dimension "d676" Radius = 0.5
  dimension "d677" Radius = 0.2
  dimension "d680" distance = 40
  dimension "d681" distance = 6
  dimension "d691" distance = 2.54
  dimension "d692" distance = 0.5 (= "d689")
  dimension "d693" distance = 0.5
  dimension "d696" distance = 0.5
  dimension "d697" distance = 5
  dimension "d701" distance = 1.7
  dimension "d702" distance = 1.7 (= "d701")
  dimension "d706" distance = 2.54 (= "d691")
  dimension "d707" distance = 3.5
  dimension "d708" distance = 0.5
  dimension "d709" ProfileOffset = 0
  dimension "d710" Side1Offset = 0
  dimension "d711" TaperAngle = 0
  dimension "d712" ProfileOffset = 0
  dimension "d713" Side1Offset = 5
  dimension "d714" TaperAngle = 0
  dimension "d715" Side1Offset = 0
  dimension "d716" TaperAngle = 0
  dimension "d717" distance = 0.75
  dimension "d718" distance = 1.7
  dimension "d719" diameter = 16 (= "od_bearings")
  dimension "d720" diameter = 6 (= "hw_m4insert_d")
  dimension "d721" diameter = 4
  dimension "d722" distance = 0.25
  dimension "d723" AlongDistance = -19
  dimension "d724" TaperAngle = 0
  dimension "d725" distance = 1
  dimension "d726" ProfileOffset = 0.5
  dimension "d727" AlongDistance = 5 (= "t_bearings")
  dimension "d728" TaperAngle = 0
  dimension "d729" diameter = 4
  dimension "d730" diameter = 6 (= "hw_m4insert_d")
  dimension "d731" diameter = 16 (= "od_bearings")
  dimension "d732" distance = 1
  dimension "d733" distance = 0.25
  dimension "d734" AlongDistance = -26
  dimension "d735" TaperAngle = 0
  dimension "d736" ProfileOffset = 0.5
  dimension "d737" AlongDistance = 5 (= "t_bearings")
  dimension "d738" TaperAngle = 0
  dimension "d739" distance = 6
  dimension "d740" ProfileOffset = 0
  dimension "d741" Side1Offset = 0
  dimension "d742" TaperAngle = 0
  dimension "d743" Radius = 4
  dimension "d744" distance = -1
  dimension "d745" AlongDistance = 32
  dimension "d746" TaperAngle = 0
  dimension "d747" distance = 0.5
  dimension "d748" distance = 1
  dimension "d749" ProfileOffset = 0
  dimension "d750" AlongDistance = 3
  dimension "d751" TaperAngle = 0
  dimension "d752" ProfileOffset = 0
  dimension "d753" Side1Offset = 0
  dimension "d754" TaperAngle = 0
  dimension "d755" Side1Offset = 0
  dimension "d756" TaperAngle = 0
  dimension "d757" ProfileOffset = 0
  dimension "d758" Side1Offset = 0
  dimension "d759" TaperAngle = 0
  dimension "d760" AlongDistance = 12
  dimension "d761" TaperAngle = 0
  dimension "d762" AlongDistance = -37
  dimension "d763" TaperAngle = 0
  dimension "d764" Side1Offset = 0.5
  dimension "d765" TaperAngle = 0
  dimension "d767" Radius = 3
  dimension "d768" Radius = 2
  dimension "d770" Radius = 3
  dimension "d771" Radius = 3
  dimension "d772" distance = 3
  dimension "d773" distance = 3
  dimension "d774" Radius = 1
  dimension "d775" Radius = 0.5
  dimension "d776" Radius = 2
  dimension "d777" diameter = 5.4 (= "hw_m3insert_d")
  dimension "d778" diameter = 3.5 (= "hw_m3_thru")
  dimension "d779" Side1Offset = 0
  dimension "d780" TaperAngle = 0
  dimension "d781" Side1Offset = 0
  dimension "d782" TaperAngle = 0
  dimension "d783" Radius = 2
  dimension "d784" Radius = 2
  dimension "d785" Radius = 2
  dimension "d786" Radius = 3
  dimension "d788" Radius = 0.5
  dimension "d789" distance = 12
  dimension "d790" distance = 2
  dimension "d791" angle = 45
  dimension "d793" Radius = 2
  dimension "d794" Radius = 2
  dimension "d795" Radius = 1
  dimension "d797" Radius = 2
  dimension "d798" Radius = 1
  dimension "d799" Radius = 2
  dimension "d800" Radius = 4.5
  dimension "d801" distance = 0.275 (= "preload_bearings / 2")
  dimension "d803" distance = -0.5
  dimension "d806" distance = 3
  dimension "d807" AlongDistance = -60
  dimension "d808" distance = 3.8274 (= "d430 / 2")
  dimension "d809" distance = 0.423 (= "1 mm - 0.577 mm")
  dimension "d810" distance = 0.5
  dimension "d813" Side1Offset = 0
  dimension "d814" TaperAngle = 0
  dimension "d815" distance = 0.1
  dimension "d816" distance = 1.75
  dimension "d818" distance = 35
  dimension "d820" distance = 5
  dimension "d821" distance = 5
  dimension "d822" diameter = 4.064 (= "hw_n6_thru")
  dimension "d823" diameter = 6.6548 (= "hw_n6_flathead")
  dimension "d824" distance = 0.6
  dimension "d825" distance = 0.6 (= "d824")
  dimension "d827" TaperAngle = 0
  dimension "d828" diameter = 3.1 (= "hw_n6_thread")
  dimension "d829" Side1Offset = 0
  dimension "d830" TaperAngle = 0
  dimension "d831" distance = 4
  dimension "d832" distance = 4.477 (= "d833")
  dimension "d833" distance = 4.477 (= "d477")
  dimension "d836" diameter = 6.6548 (= "hw_n6_flathead")
  dimension "d839" Side1Offset = 0
  dimension "d840" TaperAngle = 0
  dimension "d841" distance = 0.9
  dimension "d842" angle = 50
  dimension "d843" angle = 50
  dimension "d844" distance = 8
  dimension "d845" distance = 5
  dimension "d846" diameter = 4.5
  dimension "d847" AlongDistance = -7
  dimension "d848" TaperAngle = 0
  dimension "d849" leftDistance = 0.75
  dimension "d850" ProfileOffset = 0
  dimension "d851" Side1Offset = 0
  dimension "d852" TaperAngle = 0
  dimension "d853" ProfileOffset = 0
  dimension "d854" Side1Offset = 0
  dimension "d855" TaperAngle = 0
  dimension "d856" distance = 12.7
  dimension "d857" leftDistance = 1.5
  dimension "d858" distance = 1.5454
  dimension "d859" Radius = 4
  dimension "d860" Radius = 2
  dimension "d861" Radius = 2
  dimension "d862" Radius = 4
  dimension "d863" Radius = 2
  dimension "d864" Radius = 35
  dimension "d865" Radius = 4
  dimension "d866" Radius = 1
  dimension "d869" Side1Offset = 0
  dimension "d870" TaperAngle = 0
  dimension "d872" distance = 1.5
  dimension "d873" leftDistance = 1.5
  dimension "d874" Radius = 2
  dimension "d885" distance = 27.775
  dimension "d886" distance = 30.275 (= "30 mm + preload_bearings / 2")
  dimension "d889" diameter = 3.3 (= "hw_m4_tappedwj")
  dimension "d890" distance = 5
  dimension "d891" distance = 10.275 (= "10 mm + preload_bearings / 2")
  dimension "d893" TaperAngle = 0
  dimension "d894" distance = 17.5
  dimension "d895" distance = 27.5
  dimension "d896" distance = 0.2
  dimension "d897" distance = 0.2 (= "d896")
  dimension "d900" distance = 6
  dimension "d902" distance = 3.7 (= "2 mm + 1.2 mm + 0.5 mm")
  dimension "d903" distance = 1
  dimension "d904" distance = 8
  dimension "d905" distance = 2.54
  dimension "d906" distance = 2.54
  dimension "d907" distance = 2.54
  dimension "d908" Side1Offset = 0
  dimension "d909" TaperAngle = 0
  dimension "d910" ProfileOffset = 0
  dimension "d911" Side1Offset = 0
  dimension "d912" TaperAngle = 0
  dimension "d913" leftDistance = 1.5
  dimension "d915" distance = 5.65
  dimension "d916" distance = 14.65
  dimension "d917" distance = 14.65
  dimension "d918" Side1Offset = 0
  dimension "d919" TaperAngle = 0
  dimension "d920" ChordLen = 4
  dimension "d921" ChordLen = 1
  dimension "d923" distance = 2.54
  dimension "d924" Radius = 2
sketch "Blister" plane through (0, 0, 0) normal (0, 0, 1) x axis (1, 0, 0)
  line L1 (-19.9, 44.9) -> (-19.9, 5.1)
  line L2 (19.9, 44.9) -> (-19.9, 44.9)
  line L3 (19.9, 5.1) -> (19.9, 44.9)
  line L4 (-19.9, 5.1) -> (19.9, 5.1)
  line L5 (3.85, 16.46) -> (3.85, 44.9)
  line L6 (3.35, 0) -> (3.35, 60)
  line L7 (7.49, 33.2818) -> (16.26, 33.2818)
  line L8 (6.49, 26.2818) -> (6.49, 32.2818)
  line L9 (17.26, 32.2818) -> (17.26, 26.2818)
  line L10 (19.9, 16.46) -> (3.85, 16.46)
  line L11 (2.35, 14.96) -> (19.9, 14.96)
  line L12 (2.35, 32.2818) -> (2.35, 14.96)
  line L13 (-1.9, 36.9) -> (-1.9, 42.9)
  line L14 (-19.9, 36.9) -> (-1.9, 36.9)
  line L15 (19.9, 13.1) -> (-19.9, 13.1)
  line L16 (11.9, 42.9) -> (-1.9, 42.9)
  line L17 (11.9, 36.9) -> (11.9, 42.9)
  line L18 (19.9, 36.9) -> (11.9, 36.9)
  line L19 (-3.6, 19.6596) -> (-3.6, 24.3404)
  line L20 (-3.35, 60) -> (-3.35, 0)
  line L21 (19.8, 36.9) -> (19.8, 13.1)
  line L22 (-19.8, 13.1) -> (-19.8, 36.9)
  circle C1 centre (-15, 10) radius 2.7
  circle C2 centre (-5, 10) radius 2.7
  circle C3 centre (5, 10) radius 2.7
  circle C4 centre (15, 10) radius 2.7
  circle C5 centre (15, 40) radius 2.7
  circle C6 centre (-5, 40) radius 2.7
  circle C7 centre (-15, 40) radius 2.7
  circle C8 centre (11.25, 22) radius 4.5
  circle C9 centre (11.25, 22) radius 3
  circle C10 centre (11.25, 22) radius 5.54
  arc A1 centre (6.99, 26.2818) radius 0.5 clockwise from (7.3426, 25.9274) to (6.49, 26.2818)
  arc A2 centre (16.2313, 26.2818) radius 1.0287 clockwise from (17.26, 26.2818) to (15.4512, 25.6113)
  arc A3 centre (7.49, 32.2818) radius 1 clockwise from (6.49, 32.2818) to (7.49, 33.2818)
  arc A4 centre (16.26, 32.2818) radius 1 clockwise from (16.26, 33.2818) to (17.26, 32.2818)
  arc A5 centre (3.1, 32.2818) radius 0.75 clockwise from (2.35, 32.2818) to (3.85, 32.2818)
  circle C11 centre (-11.25, 22) radius 3
  circle C12 centre (-11.25, 22) radius 4.5
  circle C13 centre (-11.25, 22) radius 8
  circle C14 centre (-11.25, 22) radius 4
  circle C15 centre (11.25, 22) radius 4
  point P6 (-15, 10)
  point P8 (-15, 10)
  point P14 (-15, 40)
  point P15 (-15, 40)
  point P13 (-5, 40)
  point P16 (-5, 40)
  point P7 (15, 40)
  point P12 (15, 40)
  point P11 (15, 10)
  point P17 (15, 10)
  point P10 (5, 10)
  point P18 (5, 10)
  point P9 (-5, 10)
  point P19 (-5, 10)
  point P20 (11.25, 22)
  point P21 (11.25, 22)
  point P22 (11.25, 22)
  point P23 (3.85, 44.9)
  point P34 (19.9, 16.46)
  point P35 (7.3426, 25.9274)
  point P30 (6.49, 26.2818)
  point P31 (17.26, 26.2818)
  point P37 (15.4512, 25.6113)
  point P27 (16.26, 33.2818)
  point P40 (16.26, 33.2818)
  point P42 (19.9, 14.96)
  point P45 (3.85, 32.2818)
  point P29 (6.49, 32.2818)
  point P47 (-11.25, 22)
  point P48 (-11.25, 22)
  point P49 (-11.25, 22)
  point P50 (-11.25, 22)
  point P55 (19.9, 13.1)
  point P58 (19.9, 36.9)
  point P52 (-1.9, 36.9)
  point P59 (-3.6, 24.3404)
  point P60 (-3.6, 19.6596)
  point P54 (-19.9, 13.1)
  point P53 (-19.9, 36.9)
  point P63 (19.8, 13.1)
  point P64 (19.8, 36.9)
  point P65 (-19.8, 36.9)
  point P66 (-19.8, 13.1)
  vertical L1
  perpendicular L1 L2
  perpendicular L2 L3
  perpendicular L3 L4
  coincident P6 P8
  equal C1 C7
  equal C1 C2
  equal C1 C3
  equal C1 C4
  equal C1 C6
  equal C1 C5
  coincident P14 P15
  coincident P13 P16
  coincident P7 P12
  coincident P11 P17
  coincident P10 P18
  coincident P9 P19
  coincident P20 P21
  coincident P21 P22
  parallel L3 L5
  coincident L2 P23
  perpendicular L3 L7
  vertical L8
  vertical L9
  concentric C9 C10
  coincident L3 P34
  perpendicular L3 L10
  tangent C10 L10
  tangent L8 A1
  coincident C10 P35
  tangent C10 A1
  horizontal P30 P31
  tangent L9 A2
  coincident C10 P37
  tangent C10 A2
  tangent L8 A3
  tangent L7 A4
  coincident P27 P40
  tangent L9 A4
  tangent L7 A3
  coincident L3 P42
  perpendicular L6 L11
  perpendicular L11 L12
  tangent L5 A5
  tangent L12 A5
  coincident L5 P45
  horizontal P29 P45
  coincident P47 P48
  coincident P47 P49
  coincident P47 P50
  perpendicular L13 L14
  perpendicular L3 L15
  coincident L3 P55
  horizontal L14
  perpendicular L13 L16
  perpendicular L2 L17
  coincident L3 P58
  perpendicular L3 L18
  coincident P52 L18
  coincident C13 P59
  coincident C13 P60
  vertical L19
  coincident L1 P54
  coincident L1 P53
  coincident L15 P63
  coincident L18 P64
  perpendicular L18 L21
  coincident L14 P65
  coincident L15 P66
  perpendicular L15 L22
  concentric C13 C14
  concentric C9 C15
  dimension "d1178" distance L4 P6 = 4.9
  dimension "d1179" distance L1 P6 = 4.9
  dimension "d1180" distance L2 P7 = 4.9
  dimension "d1181" distance L3 P7 = 4.9 (= "d1180")
  dimension "d1182" diameter C1 = 5.4 (= "hw_m3insert_d")
  dimension "d1183" diameter C8 = 9
  dimension "d1184" diameter C9 = 6 (= "hw_m4insert_d")
  dimension "d1185" distance L5 L6 = 0.5
  dimension "d1186" distance L3 L9 = 2.64
  dimension "d1187" distance L5 L8 = 2.64 (= "d1186")
  dimension "d1188" distance P29 P30 = 6
  dimension "d1189" distance C9 C10 = 2.54
  dimension "d1190" radius A1 = 0.5
  dimension "d1191" radius A3 = 1
  dimension "d1192" radius A4 = 1
  dimension "d1193" distance L10 L11 = 1.5 (= "d1194")
  dimension "d1194" distance L5 L12 = 1.5
  dimension "d1198" diameter C12 = 9
  dimension "d1199" diameter C11 = 6 (= "hw_m4insert_d")
  dimension "d1200" diameter C13 = 16 (= "od_bearings")
  dimension "d1201" distance P14 L14 = 3.1
  dimension "d1202" distance P8 L15 = 3.1
  dimension "d1204" distance P13 L13 = 3.1
  dimension "d1205" distance P13 L16 = 2.9
  dimension "d1206" distance P12 L17 = 3.1
  dimension "d1207" distance L19 L20 = 0.25
  dimension "d1230" distance L3 L21 = 0.1
  dimension "d1231" distance L1 L22 = 0.1
  dimension "d1234" distance C9 C15 = 1
  dimension "d1235" distance C11 C14 = 1 (= "d1234")
extrude "Extrude124" new body sketch "Blister" profile of L1 L2 L3 L4 C1 C2 C3 C4 C5 C6 C7 C8 C9 L5 L7 L8 L9 C10 L10 A1 A2 A3 A4 L11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 along normal blind 4.5 (= "hw_m3insert_l + 0.7 mm")
extrude "Extrude125" add sketch "Blister" profile of C8 C9 L5 L7 L8 L9 C10 L10 A1 A2 A3 A4 L11 L12 A5 C11 C12 C13 L13 L14 L15 L16 L17 L18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 no distance stored
extrude "Extrude126" sketch "Blister" profile of C8 C9 C10 C11 C12 C13 L19 blind -0.5
extrude "Extrude127" sketch "Blister" profile of C8 C9 C11 C12 blind -0.5
fillet "Fillet88" radius 0.5
extrude "Extrude130" sketch "Blister" profile of C9 C11 C14 C15 blind 25 from offset 6
chamfer "Chamfer13" distance 1
chamfer "Chamfer12" distance 0.5
fillet "Fillet90" radius 3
